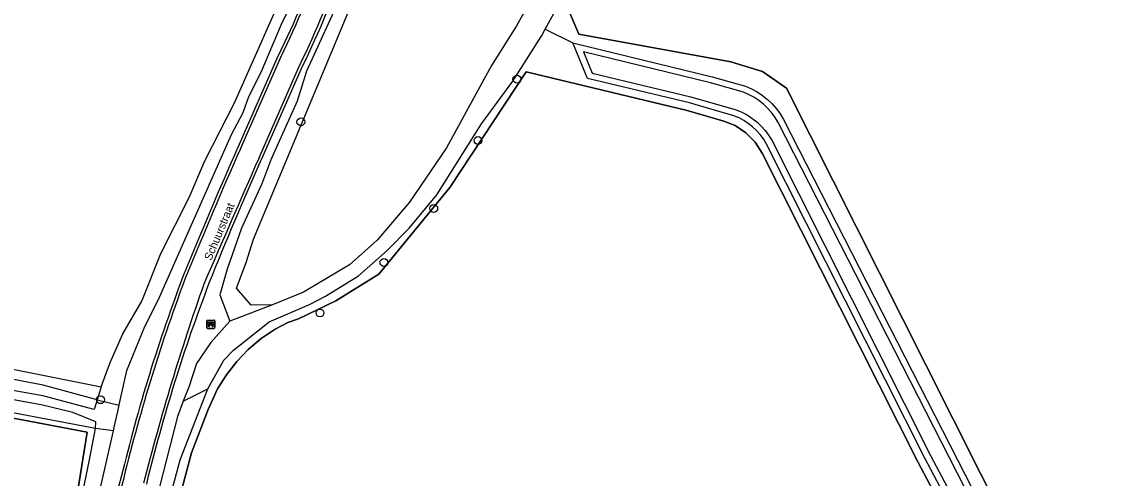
# Model space of a CAD drawing. Extents: x 164494 to 166241, y 382475 to 384494.
# Drawn here: x 165159.3 to 165296.4, y 383570.3 to 383627.3 of the extents above; entities that cross this region are included whole.
import ezdxf

# ---------------------------------------------------------------- set-up
doc = ezdxf.new("R2010")
doc.units = 0
for name, color, linetype in [('IMGEO_Bank', 7, 'Continuous'), ('IMGEO_Boom', 7, 'Continuous'), ('IMGEO_Grasland_agrarisch', 7, 'Continuous'), ('IMGEO_Grasland_overig', 7, 'Continuous'), ('IMGEO_Groenvoorziening', 7, 'Continuous'), ('IMGEO_Hek', 7, 'Continuous'), ('IMGEO_Loofbos', 7, 'Continuous'), ('IMGEO_Openbare_ruimte_label', 7, 'Continuous'), ('IMGEO_Rijbaan_lokaal_gesloten', 7, 'Continuous'), ('IMGEO_Rijbaan_lokaal_open', 7, 'Continuous'), ('IMGEO_Waterloop', 7, 'Continuous')]:
    doc.layers.add(name, color=color, linetype=linetype)

msp = doc.modelspace()

# ---------------------------------------------------------------- linework, layer by layer
at = {"layer": 'IMGEO_Bank'}
for p, q in [((165182.38, 383589.08), (165182.38, 383589.92)), ((165182.38, 383589.92), (165182.38, 383589.08)), ((165182.46, 383590), (165183.3, 383590)), ((165183.3, 383590), (165182.46, 383590)), ((165182.69, 383589.51), (165182.69, 383589.62)), ((165182.73, 383589.62), (165182.73, 383589.51)), ((165183.02, 383589.62), (165182.74, 383589.62)), ((165183.03, 383589.51), (165183.03, 383589.62)), ((165183.07, 383589.62), (165183.07, 383589.51)), ((165183.38, 383589.93), (165183.38, 383589.09)), ((165183.38, 383589.09), (165183.38, 383589.93)), ((165183.31, 383589), (165182.47, 383589)), ((165182.47, 383589), (165183.31, 383589)), ((165183.08, 383589.4), (165182.68, 383589.4)), ((165182.74, 383589.5), (165183.02, 383589.5))]:
    msp.add_line(p, q, dxfattribs=at)
for points in [[(165182.68, 383589.62), (165182.6, 383589.62), (165182.6, 383589.78), (165183.16, 383589.78), (165183.16, 383589.62), (165183.08, 383589.62)], [(165182.63, 383589.4), (165182.49, 383589.4), (165182.6, 383589.5), (165182.68, 383589.5)], [(165182.68, 383589.4), (165182.68, 383589.19), (165182.63, 383589.19), (165182.63, 383589.4)], [(165183.08, 383589.5), (165183.16, 383589.5), (165183.27, 383589.4), (165183.13, 383589.4)], [(165183.13, 383589.4), (165183.13, 383589.19), (165183.08, 383589.19), (165183.08, 383589.4)]]:
    msp.add_lwpolyline(points, dxfattribs=at)
for centre, radius, start, end in [((165182.46, 383589.93), 0.0779, 92.4484, 184.2845), ((165182.46, 383589.93), 0.0779, 92.4484, 184.2845), ((165182.68, 383589.62), 0.00671, 2.8957, 87.1043), ((165182.74, 383589.62), 0.00671, 92.8957, 177.1043), ((165183.02, 383589.62), 0.00671, 2.8957, 87.1043), ((165183.08, 383589.62), 0.00671, 92.8957, 177.1043), ((165183.3, 383589.93), 0.0779, 2.4484, 94.2845), ((165183.3, 383589.93), 0.0779, 2.4484, 94.2845), ((165182.46, 383589.08), 0.0779, 182.4484, 274.2845), ((165182.46, 383589.08), 0.0779, 182.4484, 274.2845), ((165182.63, 383589.39), 0.00671, 2.8957, 87.1043), ((165182.68, 383589.51), 0.00671, 272.8957, 357.1043), ((165182.69, 383589.39), 0.00671, 92.8957, 177.1043), ((165182.74, 383589.51), 0.00671, 182.8957, 267.1043), ((165183.02, 383589.51), 0.00671, 272.8957, 357.1043), ((165183.08, 383589.51), 0.00671, 182.8957, 267.1043), ((165183.08, 383589.39), 0.00671, 2.8957, 87.1043), ((165183.13, 383589.39), 0.00671, 92.8957, 177.1043), ((165183.3, 383589.08), 0.0779, 272.4484, 4.2845), ((165183.3, 383589.08), 0.0779, 272.4484, 4.2845)]:
    msp.add_arc(centre, radius, start, end, dxfattribs=at)
at = {"layer": 'IMGEO_Boom'}
for centre in [(165221.11, 383620.11), (165194.13, 383614.78), (165216.25, 383612.45), (165210.72, 383603.97), (165204.5, 383597.22), (165196.52, 383590.92), (165169.1, 383580.09)]:
    msp.add_circle(centre, 0.489, dxfattribs=at)
at = {"layer": 'IMGEO_Grasland_agrarisch'}
msp.add_lwpolyline([(165277.63, 383560.15), (165271.18, 383572.32), (165251.74, 383610.89), (165250.86, 383612.26), (165249.71, 383613.42), (165248.35, 383614.31), (165246.95, 383614.87), (165242.39, 383616.19), (165222.26, 383621.03), (165212.74, 383606.57), (165203.88, 383595.78), (165198.49, 383592.42), (165193.85, 383590.17), (165192.48, 383589.72), (165190.9, 383588.9), (165189.16, 383587.73), (165187.56, 383586.38), (165186.11, 383584.87), (165184.83, 383583.21), (165183.72, 383581.43), (165182.53, 383578.85), (165180.48, 383573.45), (165178.36, 383565.49)], dxfattribs=at)
at = {"layer": 'IMGEO_Grasland_overig'}
for points in [[(164964.5, 383620.21), (164972.14, 383619.93), (164987.22, 383617.3), (165008.51, 383612.87), (165025.3, 383610.21), (165102.82, 383594.97), (165169.18, 383581.72)], [(165168.67, 383580.07), (165161.94, 383581.89), (165149.5, 383584.27), (165140.61, 383585.93), (165093.97, 383594.7), (165079.66, 383597.25), (165070.61, 383598.97), (165070.56, 383596.7), (165070.61, 383595.01), (165101.7, 383589.14), (165103.58, 383588.78)], [(165168.46, 383576.5), (165107.96, 383587.93), (165105.99, 383588.31)], [(165164.33, 383556.52), (165167.42, 383576.04), (165107.84, 383587.32), (165107.52, 383585.73), (165088.86, 383468.79), (165088.13, 383468.87)]]:
    msp.add_lwpolyline(points, dxfattribs=at)
at = {"layer": 'IMGEO_Groenvoorziening'}
msp.add_lwpolyline([(165290.74, 383536.85), (165285.29, 383547.1), (165278.52, 383560.61), (165272.07, 383572.78), (165252.26, 383612.09), (165251.9, 383612.66), (165251.49, 383613.2), (165251.04, 383613.71), (165250.54, 383614.17), (165250.01, 383614.59), (165249.44, 383614.96), (165248.85, 383615.27), (165248.22, 383615.54), (165242.65, 383617.16), (165229.94, 383620.21), (165228.11, 383624.66)], dxfattribs=at)
at = {"layer": 'IMGEO_Hek'}
for points in [[(165295.91, 383537.31), (165272.21, 383584.36), (165254.77, 383618.97), (165251.77, 383621.08), (165247.82, 383622.29), (165228.83, 383625.73), (165227.32, 383629.36)], [(165178.36, 383565.49), (165180.48, 383573.45), (165182.53, 383578.85), (165183.72, 383581.43), (165184.83, 383583.21), (165186.11, 383584.87), (165187.56, 383586.38), (165189.16, 383587.73), (165190.9, 383588.9), (165192.48, 383589.72), (165193.85, 383590.17), (165198.49, 383592.42), (165203.88, 383595.78), (165212.74, 383606.57), (165222.26, 383621.03), (165242.39, 383616.19), (165246.95, 383614.87), (165248.35, 383614.31), (165249.71, 383613.42), (165250.86, 383612.26), (165251.74, 383610.89), (165271.18, 383572.32), (165277.63, 383560.15)], [(165064.91, 383595.43), (165078.35, 383592.91), (165167.42, 383576.04), (165164.33, 383556.52)]]:
    msp.add_lwpolyline(points, dxfattribs=at)
at = {"layer": 'IMGEO_Loofbos'}
for points in [[(165227.32, 383629.36), (165228.83, 383625.73), (165247.82, 383622.29), (165251.77, 383621.08), (165254.77, 383618.97), (165272.21, 383584.36), (165295.91, 383537.31), (165296.44, 383536.25)], [(165224.65, 383626.36), (165228.11, 383624.66)], [(165228.11, 383624.66), (165245.49, 383620.41), (165249.65, 383619.24), (165250.39, 383618.92), (165251.1, 383618.54), (165251.78, 383618.09), (165252.41, 383617.59), (165252.99, 383617.03), (165253.53, 383616.42), (165254.01, 383615.78), (165254.42, 383615.08), (165295.06, 383535.64), (165296.44, 383536.25)]]:
    msp.add_lwpolyline(points, dxfattribs=at)
at = {"layer": 'IMGEO_Rijbaan_lokaal_gesloten'}
for points in [[(165186.58, 383611.43), (165191.62, 383622.85)], [(165188.87, 383610.21), (165193.98, 383621.88)]]:
    msp.add_lwpolyline(points, dxfattribs=at)
for centre, radius, start, end in [((165100.88, 383667.63), 101.19, 333.7336, 349.7399), ((165102.27, 383667.15), 102.28, 333.7273, 349.8585), ((165681.12, 383391.45), 541.26, 156.0194, 157.8344), ((167629.32, 382534.91), 2666.85, 156.22097, 156.58854), ((165382.23, 383519.13), 216.37, 159.2845, 166.315), ((165452.36, 383499.04), 286.71, 160.5453, 165.738), ((165315.78, 383529.82), 149.36, 164.2685, 177.6594)]:
    msp.add_arc(centre, radius, start, end, dxfattribs=at)
at = {"layer": 'IMGEO_Rijbaan_lokaal_open'}
for points in [[(165191.31, 383623.06), (165186.25, 383611.6)], [(165189.19, 383610.09), (165194.34, 383621.73)]]:
    msp.add_lwpolyline(points, dxfattribs=at)
for centre, radius, start, end in [((165105.15, 383666.19), 96.36, 333.4092, 350.117), ((165100.49, 383667.68), 104.5, 333.913, 349.7653), ((165753.14, 383361.1), 619.77, 156.15988, 157.74926), ((165621.66, 383417.99), 473.22, 156.0496, 158.0814), ((165371.62, 383522.62), 205.56, 159.1492, 166.5449), ((165377.01, 383520.3), 208.09, 159.0691, 166.3059), ((165311.12, 383530.5), 145.03, 164.0113, 177.8491)]:
    msp.add_arc(centre, radius, start, end, dxfattribs=at)
at = {"layer": 'IMGEO_Waterloop'}
for points in [[(165262.58, 383715.44), (165258.85, 383708.81), (165253.78, 383698.25), (165247.21, 383683.31), (165244.85, 383677.39), (165242.1, 383671.3), (165237.88, 383662.58), (165233.5, 383652.62), (165222.87, 383630.04), (165221.07, 383626.75), (165217.94, 383621.8), (165212.31, 383611.54), (165207.71, 383604.74), (165203.66, 383600), (165200.19, 383596.95), (165194.45, 383593.5), (165190.57, 383591.94)], [(165207.95, 383667.8), (165207.07, 383661.55), (165206.89, 383659.05), (165205.25, 383650.42), (165203.05, 383640.62), (165199.36, 383631.04), (165194.83, 383621.12), (165193.67, 383617.35), (165190.37, 383610.05), (165189.24, 383607.03), (165186.7, 383601.51), (165184.91, 383596.38), (165183.99, 383593.17), (165185.26, 383589.88)], [(165169.18, 383581.72), (165170.3, 383584.74), (165171.9, 383588.3), (165174.27, 383592.41), (165176.62, 383598.33), (165180.17, 383605.34), (165182.14, 383609.91), (165185.82, 383617.15), (165193.02, 383633.41), (165194.75, 383638.3), (165195.56, 383641.1), (165199.64, 383665.64), (165199.66, 383665.77), (165199.8, 383666.4)], [(165171.43, 383579.41), (165171.45, 383579.46), (165172.41, 383583.72), (165174.64, 383589.23), (165176.31, 383592.53), (165185.45, 383613.19), (165186.91, 383615.96), (165187.64, 383617.96), (165189.16, 383621), (165191.71, 383626.99), (165194.54, 383632.88), (165196.21, 383636.94), (165197.08, 383640.28), (165198.07, 383645.72), (165198.13, 383647.64), (165200.59, 383659.19), (165201.73, 383666.13), (165200.72, 383666.27), (165199.8, 383666.4)], [(165190.57, 383591.94), (165187.93, 383591.91), (165186.09, 383594.01), (165187.3, 383597.22), (165188.19, 383600.12), (165202.88, 383635.28), (165204.81, 383640.44), (165205.97, 383647.55), (165207.56, 383655.75), (165208.94, 383664.31), (165209.32, 383667.69)], [(165224.65, 383626.36), (165225.91, 383628.68), (165226.39, 383629.75)], [(165182.49, 383581.46), (165184.49, 383585.03), (165185.71, 383586.29), (165190.18, 383589.82), (165195.2, 383591.98), (165197.22, 383593), (165201.31, 383595.57), (165204.91, 383598.7), (165207.68, 383601.55), (165211.11, 383605.66), (165216.7, 383614.55), (165220.59, 383619.85), (165224.21, 383625.55), (165224.65, 383626.36)], [(165294.56, 383534.87), (165253.73, 383614.7), (165253.35, 383615.34), (165252.91, 383615.93), (165252.42, 383616.48), (165251.89, 383616.99), (165251.31, 383617.45), (165250.7, 383617.85), (165250.05, 383618.21), (165249.39, 383618.49), (165245.29, 383619.64), (165229.43, 383623.52), (165230.52, 383620.88), (165242.85, 383617.92), (165248.49, 383616.29), (165249.19, 383615.99), (165249.85, 383615.64), (165250.47, 383615.23), (165251.06, 383614.77), (165251.6, 383614.26), (165252.1, 383613.71), (165252.55, 383613.11), (165252.95, 383612.48), (165272.78, 383573.14), (165279.22, 383560.97)], [(165168.67, 383580.07), (165168.31, 383578.87), (165161.89, 383580.59), (165071.9, 383596.56)], [(165190.57, 383591.94), (165185.26, 383589.88)], [(165185.26, 383589.88), (165182.88, 383587.25), (165181.09, 383584.62), (165180.12, 383581.66), (165179.44, 383579.9)], [(165168.46, 383576.5), (165168.52, 383577.35), (165165.63, 383578.51), (165161.71, 383579.46), (165113.93, 383588.11), (165108.16, 383589.15), (165106.17, 383589.51), (165105.99, 383588.31)], [(165169.18, 383581.72), (165168.67, 383580.07)], [(165171.06, 383494.09), (165171.3, 383500), (165171.84, 383506.61), (165172.02, 383519.84), (165172.64, 383528.6), (165172.59, 383531.72), (165172.95, 383534.28), (165173.08, 383538.54), (165173.53, 383543.94), (165174.06, 383547.66), (165174.41, 383551.58), (165175.21, 383555.79), (165175.64, 383558.87), (165176.67, 383563.73), (165179.05, 383572.6), (165182.49, 383581.46)], [(165179.44, 383579.9), (165182.49, 383581.46)], [(165168.67, 383580.07), (165171.43, 383579.41)], [(165179.44, 383579.9), (165178.7, 383578), (165174.14, 383560.1), (165172.75, 383551.56), (165171.27, 383535.82), (165170.7, 383525.31), (165170.31, 383514.89), (165170.06, 383500), (165168.97, 383484.32), (165168.72, 383467.34), (165168.76, 383458.42), (165169.05, 383455.04), (165169.28, 383453.05), (165169.73, 383450.81), (165170.24, 383448.79), (165171.08, 383448.15), (165171.95, 383448.11), (165172.01, 383448.23)], [(165170.71, 383576.2), (165170.85, 383576.82), (165171.26, 383578.63), (165171.43, 383579.41)], [(165161.13, 383519.91), (165161.45, 383519.65), (165162.83, 383519.67), (165163.04, 383519.85), (165163.43, 383533.8), (165165.53, 383551.96), (165167.37, 383562.39), (165168.76, 383567.63), (165170.71, 383576.2)], [(165164.33, 383556.52), (165166.35, 383565.77), (165167.07, 383569.32), (165167.77, 383572.79), (165168.46, 383576.5)], [(165170.71, 383576.2), (165168.46, 383576.5)]]:
    msp.add_lwpolyline(points, dxfattribs=at)

# ---------------------------------------------------------------- texts
at = {"layer": 'IMGEO_Openbare_ruimte_label'}
msp.add_text('Schuurstraat', height=1, rotation=67.1775, dxfattribs=at).set_placement((165182.93, 383597.4))

doc.saveas('drawing.dxf')
